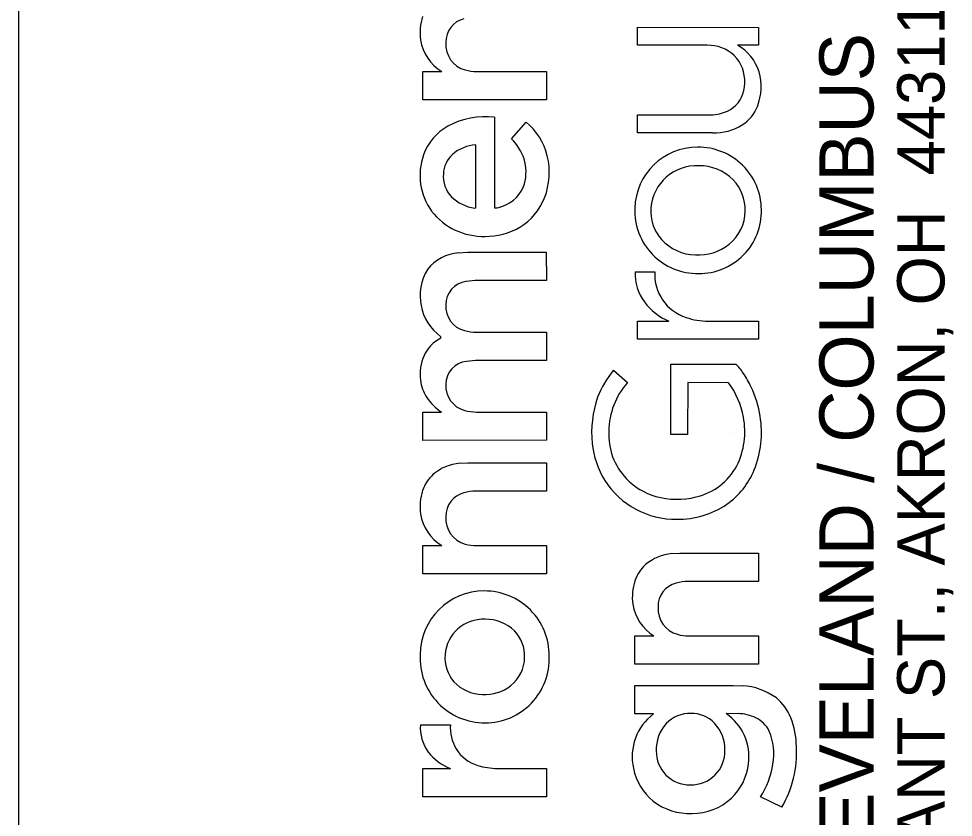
# Model space of a CAD drawing. Extents: x -4.9 to 34, y -1.2 to 22.
# Drawn here: x 32 to 32.984, y 3.594 to 4.436 of the extents above; entities that cross this region are included whole.
import ezdxf

# ---------------------------------------------------------------- set-up
doc = ezdxf.new("R2010")
doc.units = 0
doc.layers.add('SH_Border', color=7, linetype='Continuous')
doc.layers.add('SH_Data', color=7, linetype='Continuous')

msp = doc.modelspace()

# ---------------------------------------------------------------- linework, layer by layer
at = {"layer": 'SH_Border'}
msp.add_line((32, 0.5), (32, 21.5), dxfattribs=at)
at = {"layer": 'SH_Data'}
for p, q in [((32.65152, 4.40801), (32.65153, 4.42672)), ((32.65153, 4.42672), (32.7791, 4.42664)), ((32.7791, 4.42664), (32.77908, 4.40796)), ((32.7249, 4.40796), (32.65152, 4.40801)), ((32.7328, 4.40727), (32.7249, 4.40796)), ((32.77908, 4.40796), (32.75689, 4.40796)), ((32.42542, 4.38016), (32.44552, 4.38021)), ((32.42542, 4.35035), (32.42542, 4.38016)), ((32.48222, 4.38021), (32.55569, 4.38021)), ((32.55569, 4.38021), (32.55571, 4.35045)), ((32.55571, 4.35045), (32.42542, 4.35035)), ((32.50108, 4.33209), (32.50118, 4.23657)), ((32.65154, 4.33443), (32.72905, 4.3345)), ((32.65165, 4.31543), (32.65154, 4.33443)), ((32.51882, 4.30927), (32.53422, 4.32662)), ((32.73073, 4.31543), (32.65165, 4.31543)), ((32.48144, 4.23644), (32.48144, 4.30296)), ((32.48016, 4.23628), (32.48144, 4.23644)), ((32.46329, 4.18915), (32.47259, 4.18968)), ((32.47259, 4.18968), (32.55557, 4.18968)), ((32.55557, 4.18968), (32.55571, 4.15982)), ((32.64932, 4.16907), (32.66978, 4.16907)), ((32.48058, 4.15981), (32.47102, 4.15881)), ((32.55571, 4.15982), (32.48058, 4.15981)), ((32.65152, 4.11699), (32.68476, 4.117)), ((32.65152, 4.098), (32.65152, 4.11699)), ((32.72605, 4.11703), (32.7791, 4.11696)), ((32.7791, 4.11696), (32.77903, 4.098)), ((32.48218, 4.10553), (32.55571, 4.10548)), ((32.55571, 4.10548), (32.55571, 4.07568)), ((32.44443, 4.09922), (32.44455, 4.10072)), ((32.77903, 4.098), (32.65152, 4.098)), ((32.4809, 4.07567), (32.47143, 4.07474)), ((32.55571, 4.07568), (32.4809, 4.07567)), ((32.62636, 4.06548), (32.64114, 4.05241)), ((32.6868, 4.07185), (32.75516, 4.07192)), ((32.6868, 3.99778), (32.6868, 4.07185)), ((32.70448, 4.05241), (32.70432, 3.99775)), ((32.74737, 4.05227), (32.70448, 4.05241)), ((32.42542, 3.99152), (32.42545, 4.02138)), ((32.42545, 4.02138), (32.44515, 4.02138)), ((32.48206, 4.02138), (32.55571, 4.02136)), ((32.55571, 4.02136), (32.55571, 3.99156)), ((32.70432, 3.99775), (32.6868, 3.99778)), ((32.75, 4), (32.75, 4)), ((32.55571, 3.99156), (32.42542, 3.99152)), ((32.46439, 3.96736), (32.47289, 3.96783)), ((32.47289, 3.96783), (32.55571, 3.96783)), ((32.55571, 3.96783), (32.55571, 3.93804)), ((32.55571, 3.93804), (32.4814, 3.93796)), ((32.42542, 3.88066), (32.44552, 3.88071)), ((32.42542, 3.85086), (32.42542, 3.88066)), ((32.48222, 3.88071), (32.55569, 3.88071)), ((32.55569, 3.88071), (32.55571, 3.85096)), ((32.68784, 3.8722), (32.69634, 3.87266)), ((32.69634, 3.87266), (32.77916, 3.87266)), ((32.77916, 3.87266), (32.77917, 3.84287)), ((32.55571, 3.85096), (32.42542, 3.85086)), ((32.77917, 3.84287), (32.70485, 3.8428)), ((32.64888, 3.7855), (32.66897, 3.78555)), ((32.64888, 3.75569), (32.64888, 3.7855)), ((32.70568, 3.78555), (32.77915, 3.78555)), ((32.77915, 3.78555), (32.77917, 3.75579)), ((32.77917, 3.75579), (32.64888, 3.75569)), ((32.6489, 3.70336), (32.64889, 3.73322)), ((32.64889, 3.73322), (32.75236, 3.73322)), ((32.75236, 3.73322), (32.76191, 3.73285)), ((32.66836, 3.70336), (32.6489, 3.70336)), ((32.75763, 3.70356), (32.74487, 3.70361)), ((32.42299, 3.69193), (32.45454, 3.69193)), ((32.42542, 3.64577), (32.45473, 3.64579)), ((32.42542, 3.61593), (32.42542, 3.64577)), ((32.50413, 3.64581), (32.55571, 3.64573)), ((32.55571, 3.64573), (32.55565, 3.61593)), ((32.55565, 3.61593), (32.42542, 3.61593)), ((32.8036, 3.60491), (32.7812, 3.61598))]:
    msp.add_line(p, q, dxfattribs=at)
for points in [[(32.7328, 4.40727), (32.7249, 4.40796), (32.65152, 4.40801), (32.65153, 4.42672), (32.7791, 4.42664), (32.77908, 4.40796), (32.75689, 4.40796)], [(32.42542, 4.35035), (32.42542, 4.38016), (32.44552, 4.38021)], [(32.48222, 4.38021), (32.55569, 4.38021), (32.55571, 4.35045), (32.42542, 4.35035)], [(32.50108, 4.33209), (32.50118, 4.23657)], [(32.73073, 4.31543), (32.65165, 4.31543), (32.65154, 4.33443), (32.72905, 4.3345)], [(32.51882, 4.30927), (32.53422, 4.32662)], [(32.48016, 4.23628), (32.48144, 4.23644), (32.48144, 4.30296)], [(32.46329, 4.18915), (32.47259, 4.18968), (32.55557, 4.18968), (32.55571, 4.15982), (32.48058, 4.15981), (32.47102, 4.15881)], [(32.64932, 4.16907), (32.66978, 4.16907)], [(32.72605, 4.11703), (32.7791, 4.11696), (32.77903, 4.098), (32.65152, 4.098)], [(32.65152, 4.098), (32.65152, 4.11699), (32.68476, 4.117)], [(32.48218, 4.10553), (32.55571, 4.10548), (32.55571, 4.07568), (32.4809, 4.07567), (32.47143, 4.07474)], [(32.44443, 4.09922), (32.44455, 4.10072)], [(32.62636, 4.06548), (32.64114, 4.05241)], [(32.74737, 4.05227), (32.70448, 4.05241), (32.70432, 3.99775), (32.6868, 3.99778), (32.6868, 4.07185), (32.75516, 4.07192)], [(32.42542, 3.99152), (32.42545, 4.02138), (32.44515, 4.02138)], [(32.48206, 4.02138), (32.55571, 4.02136), (32.55571, 3.99156), (32.42542, 3.99152)], [(32.46439, 3.96736), (32.47289, 3.96783), (32.55571, 3.96783), (32.55571, 3.93804), (32.4814, 3.93796)], [(32.42542, 3.85086), (32.42542, 3.88066), (32.44552, 3.88071)], [(32.48222, 3.88071), (32.55569, 3.88071), (32.55571, 3.85096), (32.42542, 3.85086)], [(32.68784, 3.8722), (32.69634, 3.87266), (32.77916, 3.87266), (32.77917, 3.84287), (32.70485, 3.8428)], [(32.64888, 3.75569), (32.64888, 3.7855), (32.66897, 3.78555)], [(32.70568, 3.78555), (32.77915, 3.78555), (32.77917, 3.75579), (32.64888, 3.75569)], [(32.66836, 3.70336), (32.6489, 3.70336), (32.64889, 3.73322), (32.75236, 3.73322), (32.76191, 3.73285)], [(32.75763, 3.70356), (32.74487, 3.70361)], [(32.42299, 3.69193), (32.45454, 3.69193)], [(32.50413, 3.64581), (32.55571, 3.64573), (32.55565, 3.61593), (32.42542, 3.61593)], [(32.42542, 3.61593), (32.42542, 3.64577), (32.45473, 3.64579)], [(32.8036, 3.60491), (32.7812, 3.61598)]]:
    msp.add_lwpolyline(points, dxfattribs=at)
for centre, radius, start, end in [((32.47872, 4.42108), 0.05602, 162.27398, 187.79173), ((32.47872, 4.42108), 0.05602, 162.27398, 187.79173), ((32.47482, 4.41155), 0.02498, 103.68683, 182.21395), ((32.47482, 4.41155), 0.02498, 103.68683, 182.21395), ((32.47027, 4.4209), 0.04763, 188.96462, 238.69865), ((32.47027, 4.4209), 0.04763, 188.96462, 238.69865), ((32.47735, 4.40846), 0.02757, 175.58441, 255.13816), ((32.47735, 4.40846), 0.02757, 175.58441, 255.13816), ((32.72711, 4.36998), 0.03772, 33.50082, 81.32954), ((32.72711, 4.36998), 0.03772, 33.50082, 81.32954), ((32.73239, 4.36485), 0.04959, 17.62209, 60.38974), ((32.73239, 4.36485), 0.04959, 17.62209, 60.38974), ((32.72414, 4.3695), 0.04048, 346.56179, 31.75389), ((32.72414, 4.3695), 0.04048, 346.56179, 31.75389), ((32.48183, 4.42235), 0.04215, 254.08913, 270.52838), ((32.48183, 4.42235), 0.04215, 254.08913, 270.52838), ((32.72343, 4.36415), 0.05838, 339.16197, 15.61485), ((32.72343, 4.36415), 0.05838, 339.16197, 15.61485), ((32.73371, 4.36616), 0.03042, 294.63214, 348.48625), ((32.73371, 4.36616), 0.03042, 294.63214, 348.48625), ((32.739, 4.35901), 0.04201, 303.10391, 338.15613), ((32.739, 4.35901), 0.04201, 303.10391, 338.15613), ((32.49176, 4.24874), 0.08387, 83.62118, 118.28448), ((32.49176, 4.24874), 0.08387, 83.62118, 118.28448), ((32.72747, 4.38081), 0.04633, 271.95199, 294.08943), ((32.72747, 4.38081), 0.04633, 271.95199, 294.08943), ((32.47894, 4.27368), 0.05583, 118.82935, 160.62242), ((32.47894, 4.27368), 0.05583, 118.82935, 160.62242), ((32.49399, 4.2763), 0.06443, 13.53275, 51.36266), ((32.49399, 4.2763), 0.06443, 13.53275, 51.36266), ((32.7321, 4.37256), 0.05715, 268.62699, 301.47779), ((32.7321, 4.37256), 0.05715, 268.62699, 301.47779), ((32.4844, 4.26071), 0.04236, 94.01311, 130.88062), ((32.4844, 4.26071), 0.04236, 94.01311, 130.88062), ((32.48033, 4.27018), 0.05485, 19.0387, 45.44322), ((32.48033, 4.27018), 0.05485, 19.0387, 45.44322), ((32.48697, 4.27074), 0.06438, 160.52138, 215.78155), ((32.48697, 4.27074), 0.06438, 160.52138, 215.78155), ((32.47703, 4.2709), 0.02985, 132.98553, 177.1802), ((32.47703, 4.2709), 0.02985, 132.98553, 177.1802), ((32.48289, 4.27384), 0.0758, 339.35431, 13.37708), ((32.48289, 4.27384), 0.0758, 339.35431, 13.37708), ((32.71435, 4.23484), 0.06552, 89.48213, 178.77752), ((32.71435, 4.23484), 0.06552, 89.48213, 178.77752), ((32.71582, 4.23414), 0.06623, 0.42265, 90.7613), ((32.71582, 4.23414), 0.06623, 0.42265, 90.7613), ((32.48724, 4.27433), 0.04701, 344.60723, 17.00675), ((32.48724, 4.27433), 0.04701, 344.60723, 17.00675), ((32.47824, 4.26966), 0.03114, 175.00138, 223.2876), ((32.47824, 4.26966), 0.03114, 175.00138, 223.2876), ((32.71397, 4.23244), 0.04846, 87.68827, 175.01696), ((32.71397, 4.23244), 0.04846, 87.68827, 175.01696), ((32.71659, 4.23036), 0.05052, 44.91202, 90.75914), ((32.71659, 4.23036), 0.05052, 44.91202, 90.75914), ((32.49895, 4.27177), 0.03504, 288.01084, 343.55364), ((32.49895, 4.27177), 0.03504, 288.01084, 343.55364), ((32.71955, 4.23452), 0.04549, 358.32279, 43.83486), ((32.71955, 4.23452), 0.04549, 358.32279, 43.83486), ((32.48546, 4.27826), 0.04232, 225.06454, 262.79701), ((32.48546, 4.27826), 0.04232, 225.06454, 262.79701), ((32.49548, 4.26982), 0.0626, 300.94393, 338.73223), ((32.49548, 4.26982), 0.0626, 300.94393, 338.73223), ((32.48908, 4.27516), 0.06872, 217.74341, 271.65606), ((32.48908, 4.27516), 0.06872, 217.74341, 271.65606), ((32.50129, 4.25678), 0.02021, 269.70042, 294.87295), ((32.50129, 4.25678), 0.02021, 269.70042, 294.87295), ((32.71483, 4.2334), 0.06606, 177.53728, 270.94524), ((32.71483, 4.2334), 0.06606, 177.53728, 270.94524), ((32.71085, 4.23311), 0.0453, 175.51467, 221.42047), ((32.71085, 4.23311), 0.0453, 175.51467, 221.42047), ((32.71671, 4.23271), 0.06536, 269.30834, 1.67905), ((32.71671, 4.23271), 0.06536, 269.30834, 1.67905), ((32.71931, 4.23374), 0.04572, 308.90382, 359.30947), ((32.71931, 4.23374), 0.04572, 308.90382, 359.30947), ((32.49204, 4.27702), 0.07055, 269.20529, 300.33566), ((32.49204, 4.27702), 0.07055, 269.20529, 300.33566), ((32.71399, 4.23734), 0.05046, 222.66255, 268.37331), ((32.71399, 4.23734), 0.05046, 222.66255, 268.37331), ((32.71567, 4.23859), 0.05178, 266.55312, 308.67253), ((32.71567, 4.23859), 0.05178, 266.55312, 308.67253), ((32.46638, 4.14404), 0.04521, 93.91118, 142.30723), ((32.46638, 4.14404), 0.04521, 93.91118, 142.30723), ((32.47585, 4.14373), 0.05319, 148.28793, 233.9556), ((32.47585, 4.14373), 0.05319, 148.28793, 233.9556), ((32.69878, 4.16662), 0.04952, 177.16211, 216.28024), ((32.69878, 4.16662), 0.04952, 177.16211, 216.28024), ((32.71735, 4.16638), 0.04764, 176.76988, 252.15044), ((32.71735, 4.16638), 0.04764, 176.76988, 252.15044), ((32.47384, 4.13499), 0.02399, 96.75763, 181.6251), ((32.47384, 4.13499), 0.02399, 96.75763, 181.6251), ((32.47577, 4.13241), 0.02597, 175.81573, 256.16716), ((32.47577, 4.13241), 0.02597, 175.81573, 256.16716), ((32.70975, 4.17555), 0.06366, 216.91526, 246.88619), ((32.70975, 4.17555), 0.06366, 216.91526, 246.88619), ((32.7269, 4.19175), 0.07473, 251.13884, 269.34694), ((32.7269, 4.19175), 0.07473, 251.13884, 269.34694), ((32.4817, 4.15053), 0.04501, 254.34629, 270.61033), ((32.4817, 4.15053), 0.04501, 254.34629, 270.61033), ((32.4638, 4.06267), 0.04137, 117.91625, 139.24296), ((32.4638, 4.06267), 0.04137, 117.91625, 139.24296), ((32.46194, 4.06452), 0.03875, 139.52447, 154.84698), ((32.46194, 4.06452), 0.03875, 139.52447, 154.84698), ((32.47144, 4.0612), 0.04877, 156.06382, 187.3493), ((32.47144, 4.0612), 0.04877, 156.06382, 187.3493), ((32.47421, 4.05056), 0.02434, 96.5532, 179.94902), ((32.47421, 4.05056), 0.02434, 96.5532, 179.94902), ((32.70163, 4.00187), 0.09855, 139.79476, 159.13696), ((32.70163, 4.00187), 0.09855, 139.79476, 159.13696), ((32.72498, 4.03937), 0.04438, 30.98913, 47.16099), ((32.72498, 4.03937), 0.04438, 30.98913, 47.16099), ((32.46461, 4.05974), 0.04181, 186.5579, 213.38846), ((32.46461, 4.05974), 0.04181, 186.5579, 213.38846), ((32.67091, 4.00018), 0.11106, 25.30315, 33.96179), ((32.67091, 4.00018), 0.11106, 25.30315, 33.96179), ((32.47608, 4.04863), 0.02628, 175.722, 255.78627), ((32.47608, 4.04863), 0.02628, 175.722, 255.78627), ((32.69899, 4.00079), 0.07753, 138.25804, 179.70064), ((32.69899, 4.00079), 0.07753, 138.25804, 179.70064), ((32.67889, 4.00099), 0.08556, 10.07509, 36.83189), ((32.67889, 4.00099), 0.08556, 10.07509, 36.83189), ((32.6704, 3.99987), 0.11166, 8.80339, 25.33484), ((32.6704, 3.99987), 0.11166, 8.80339, 25.33484), ((32.47886, 4.07078), 0.0598, 214.70433, 235.68724), ((32.47886, 4.07078), 0.0598, 214.70433, 235.68724), ((32.7187, 3.99968), 0.11536, 161.14379, 185.62812), ((32.7187, 3.99968), 0.11536, 161.14379, 185.62812), ((32.48195, 4.06518), 0.0438, 253.66719, 270.14979), ((32.48195, 4.06518), 0.0438, 253.66719, 270.14979), ((32.68425, 4.00057), 0.08036, 333.46689, 11.03668), ((32.68425, 4.00057), 0.08036, 333.46689, 11.03668), ((32.67564, 3.99977), 0.10649, 338.28866, 9.28548), ((32.67564, 3.99977), 0.10649, 338.28866, 9.28548), ((32.68811, 3.99732), 0.06676, 176.66577, 223.6912), ((32.68811, 3.99732), 0.06676, 176.66577, 223.6912), ((32.69336, 3.99699), 0.08987, 185.50773, 212.01294), ((32.69336, 3.99699), 0.08987, 185.50773, 212.01294), ((32.46871, 3.91767), 0.04988, 94.97056, 130.22484), ((32.46871, 3.91767), 0.04988, 94.97056, 130.22484), ((32.69868, 3.99547), 0.0652, 282.88151, 331.81475), ((32.69868, 3.99547), 0.0652, 282.88151, 331.81475), ((32.69835, 3.99168), 0.08241, 305.03061, 337.67573), ((32.69835, 3.99168), 0.08241, 305.03061, 337.67573), ((32.46348, 3.92602), 0.04016, 132.22383, 161.68229), ((32.46348, 3.92602), 0.04016, 132.22383, 161.68229), ((32.69211, 3.99748), 0.08908, 212.70222, 270.71399), ((32.69211, 3.99748), 0.08908, 212.70222, 270.71399), ((32.69045, 4.00011), 0.07039, 224.02147, 253.88), ((32.69045, 4.00011), 0.07039, 224.02147, 253.88), ((32.47872, 3.92158), 0.05602, 162.27398, 187.79173), ((32.47872, 3.92158), 0.05602, 162.27398, 187.79173), ((32.48108, 3.89196), 0.04601, 89.60515, 105.33026), ((32.48108, 3.89196), 0.04601, 89.60515, 105.33026), ((32.47482, 3.91206), 0.02498, 103.68683, 182.21395), ((32.47482, 3.91206), 0.02498, 103.68683, 182.21395), ((32.69318, 4.01254), 0.08309, 254.45353, 283.9512), ((32.69318, 4.01254), 0.08309, 254.45353, 283.9512), ((32.69429, 3.99979), 0.09138, 269.3273, 304.19632), ((32.69429, 3.99979), 0.09138, 269.3273, 304.19632), ((32.47027, 3.92141), 0.04763, 188.96462, 238.69865), ((32.47027, 3.92141), 0.04763, 188.96462, 238.69865), ((32.47735, 3.90897), 0.02757, 175.58441, 255.13816), ((32.47735, 3.90897), 0.02757, 175.58441, 255.13816), ((32.48183, 3.92286), 0.04215, 254.08913, 270.52838), ((32.48183, 3.92286), 0.04215, 254.08913, 270.52838), ((32.69216, 3.82251), 0.04988, 94.97056, 130.22484), ((32.69216, 3.82251), 0.04988, 94.97056, 130.22484), ((32.68694, 3.83085), 0.04016, 132.22383, 161.68229), ((32.68694, 3.83085), 0.04016, 132.22383, 161.68229), ((32.70217, 3.82642), 0.05602, 162.27398, 187.79173), ((32.70217, 3.82642), 0.05602, 162.27398, 187.79173), ((32.69828, 3.81689), 0.02498, 103.68683, 182.21395), ((32.69828, 3.81689), 0.02498, 103.68683, 182.21395), ((32.70453, 3.79679), 0.04601, 89.60515, 105.33026), ((32.70453, 3.79679), 0.04601, 89.60515, 105.33026), ((32.49014, 3.76543), 0.0674, 89.84756, 179.64047), ((32.49014, 3.76543), 0.0674, 89.84756, 179.64047), ((32.49057, 3.76474), 0.0681, 359.54009, 90.21138), ((32.49057, 3.76474), 0.0681, 359.54009, 90.21138), ((32.69372, 3.82624), 0.04763, 188.96462, 238.69865), ((32.69372, 3.82624), 0.04763, 188.96462, 238.69865), ((32.7008, 3.81381), 0.02757, 175.58441, 255.13816), ((32.7008, 3.81381), 0.02757, 175.58441, 255.13816), ((32.48923, 3.76263), 0.0404, 87.04809, 175.57259), ((32.48923, 3.76263), 0.0404, 87.04809, 175.57259), ((32.49204, 3.75999), 0.04299, 45.84264, 90.98008), ((32.49204, 3.75999), 0.04299, 45.84264, 90.98008), ((32.49458, 3.76421), 0.03821, 357.88569, 44.15902), ((32.49458, 3.76421), 0.03821, 357.88569, 44.15902), ((32.70529, 3.82769), 0.04215, 254.08913, 270.52838), ((32.70529, 3.82769), 0.04215, 254.08913, 270.52838), ((32.49083, 3.76209), 0.06819, 176.8344, 270.40384), ((32.49083, 3.76209), 0.06819, 176.8344, 270.40384), ((32.48729, 3.7625), 0.03848, 175.15378, 221.14706), ((32.48729, 3.7625), 0.03848, 175.15378, 221.14706), ((32.49123, 3.76139), 0.06749, 270.06243, 2.37759), ((32.49123, 3.76139), 0.06749, 270.06243, 2.37759), ((32.49446, 3.76318), 0.0383, 308.28936, 359.43468), ((32.49446, 3.76318), 0.0383, 308.28936, 359.43468), ((32.48919, 3.76607), 0.04228, 223.09994, 268.80895), ((32.48919, 3.76607), 0.04228, 223.09994, 268.80895), ((32.49096, 3.7679), 0.04418, 266.56515, 308.06078), ((32.49096, 3.7679), 0.04418, 266.56515, 308.06078), ((32.75907, 3.66789), 0.06503, 53.40344, 87.49062), ((32.75907, 3.66789), 0.06503, 53.40344, 87.49062), ((32.76517, 3.68039), 0.05141, 21.60748, 50.5577), ((32.76517, 3.68039), 0.05141, 21.60748, 50.5577), ((32.70292, 3.65813), 0.05692, 127.37482, 192.22468), ((32.70292, 3.65813), 0.05692, 127.37482, 192.22468), ((32.70693, 3.66927), 0.0346, 88.47302, 136.42562), ((32.70693, 3.66927), 0.0346, 88.47302, 136.42562), ((32.70814, 3.66963), 0.03424, 44.27195, 90.47623), ((32.70814, 3.66963), 0.03424, 44.27195, 90.47623), ((32.71421, 3.65829), 0.05472, 352.1125, 55.92295), ((32.71421, 3.65829), 0.05472, 352.1125, 55.92295), ((32.75666, 3.65725), 0.04633, 65.01687, 88.8011), ((32.75666, 3.65725), 0.04633, 65.01687, 88.8011), ((32.46616, 3.68882), 0.04329, 175.87313, 216.34747), ((32.46616, 3.68882), 0.04329, 175.87313, 216.34747), ((32.50087, 3.68948), 0.04639, 176.9688, 209.60636), ((32.50087, 3.68948), 0.04639, 176.9688, 209.60636), ((32.71141, 3.66602), 0.0401, 137.46739, 182.33237), ((32.71141, 3.66602), 0.0401, 137.46739, 182.33237), ((32.70368, 3.666), 0.03996, 358.57141, 43.53765), ((32.70368, 3.666), 0.03996, 358.57141, 43.53765), ((32.7626, 3.67155), 0.03085, 26.26808, 63.80301), ((32.7626, 3.67155), 0.03085, 26.26808, 63.80301), ((32.73069, 3.66714), 0.08835, 1.15143, 21.3627), ((32.73069, 3.66714), 0.08835, 1.15143, 21.3627), ((32.73565, 3.66154), 0.05953, 349.30734, 23.43071), ((32.73565, 3.66154), 0.05953, 349.30734, 23.43071), ((32.47466, 3.69716), 0.05511, 218.09809, 248.7907), ((32.47466, 3.69716), 0.05511, 218.09809, 248.7907), ((32.49514, 3.68814), 0.04079, 211.94466, 253.2028), ((32.49514, 3.68814), 0.04079, 211.94466, 253.2028), ((32.70645, 3.6637), 0.03511, 178.88208, 271.08374), ((32.70645, 3.6637), 0.03511, 178.88208, 271.08374), ((32.70818, 3.66404), 0.03546, 268.27882, 1.55016), ((32.70818, 3.66404), 0.03546, 268.27882, 1.55016), ((32.70538, 3.66244), 0.11383, 329.6388, 3.25998), ((32.70538, 3.66244), 0.11383, 329.6388, 3.25998), ((32.50465, 3.7165), 0.07069, 252.46555, 269.57296), ((32.50465, 3.7165), 0.07069, 252.46555, 269.57296), ((32.70463, 3.65696), 0.05837, 190.75182, 231.28919), ((32.70463, 3.65696), 0.05837, 190.75182, 231.28919), ((32.70988, 3.65708), 0.05887, 313.74196, 353.8554), ((32.70988, 3.65708), 0.05887, 313.74196, 353.8554), ((32.70738, 3.66334), 0.08771, 327.31495, 351.57478), ((32.70738, 3.66334), 0.08771, 327.31495, 351.57478), ((32.70954, 3.65901), 0.06051, 269.6361, 312.70877), ((32.70954, 3.65901), 0.06051, 269.6361, 312.70877), ((32.70632, 3.66112), 0.06269, 232.46061, 272.59022), ((32.70632, 3.66112), 0.06269, 232.46061, 272.59022)]:
    msp.add_arc(centre, radius, start, end, dxfattribs=at)

# ---------------------------------------------------------------- texts
for s, height, p in [('450 GRANT ST., AKRON, OH  44311', 0.0498462, (32.97489, 3.33738)), ('AKRON / CLEVELAND / COLUMBUS', 0.056969, (32.90012, 3.138))]:
    msp.add_text(s, height=height, rotation=90, dxfattribs=at).set_placement(p)

doc.saveas('drawing.dxf')
